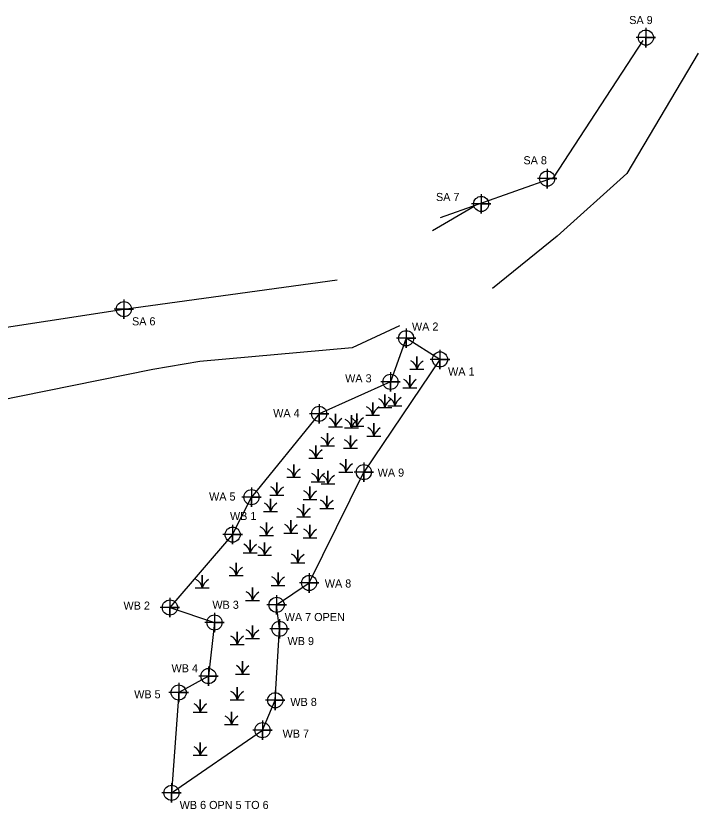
# Model space of a CAD drawing. Extents: x 2058476 to 2058911, y 688598 to 689103.
# Drawn here: x 2058700 to 2058910.8, y 688598.2 to 688843.3 of the extents above; entities that cross this region are included whole.
import ezdxf

# ---------------------------------------------------------------- set-up
doc = ezdxf.new("R2010")
doc.units = 0
for name, color, linetype in [('Exist Environmental Wetland Boundary', 7, 'Continuous'), ('Exist Environmental Wetland Boundary Cogo Comment', 7, 'Continuous'), ('Exist Environmental Wetland Boundary Cogo Point CELL', 7, 'Continuous'), ('Exist Hydro Jurisdictional Stream or Body of Water NEU Mitigable', 7, 'Continuous'), ('Exist Hydro Jurisdictional Stream or Body of Water NEU Mitigable Cogo Comment', 7, 'Continuous'), ('Exist Hydro Jurisdictional Stream or Body of Water NEU Mitigable Cogo Point CELL', 7, 'Continuous'), ('Exist Hydro Swamp or Marsh', 7, 'Continuous')]:
    doc.layers.add(name, color=color, linetype=linetype)

msp = doc.modelspace()

# ---------------------------------------------------------------- linework, layer by layer
at = {"layer": 'Exist Environmental Wetland Boundary'}
for p, q in [((2058831.07, 688737.12), (2058807.52, 688702.3)), ((2058767, 688682.98), (2058772.83, 688694.56)), ((2058781.46, 688653.85), (2058780.59, 688661.27))]:
    msp.add_line(p, q, dxfattribs=at)
for points in [[(2058831.07, 688737.12), (2058820.62, 688743.65), (2058815.77, 688730.19), (2058793.71, 688720.32), (2058772.83, 688694.56)], [(2058780.59, 688661.27), (2058790.64, 688668.04), (2058807.52, 688702.3)], [(2058767, 688682.98), (2058747.61, 688660.45), (2058761.37, 688655.84), (2058759.51, 688639.28), (2058750.32, 688634.18), (2058748.12, 688603.2), (2058776.2, 688622.56), (2058780.17, 688631.79), (2058781.46, 688653.85)], [(2058767, 688682.98), (2058747.61, 688660.45), (2058761.37, 688655.84), (2058759.51, 688639.28), (2058750.32, 688634.18), (2058748.12, 688603.2), (2058776.2, 688622.56), (2058780.17, 688631.79), (2058781.46, 688653.85)]]:
    msp.add_lwpolyline(points, dxfattribs=at)
at = {"layer": 'Exist Environmental Wetland Boundary Cogo Point CELL'}
for points in [[(2058820.62, 688746.65), (2058820.62, 688740.65), (2058820.62, 688743.65), (2058823.62, 688743.65), (2058817.62, 688743.65)], [(2058831.07, 688740.12), (2058831.07, 688734.12), (2058831.07, 688737.12), (2058834.07, 688737.12), (2058828.07, 688737.12)], [(2058815.77, 688733.19), (2058815.77, 688727.19), (2058815.77, 688730.19), (2058818.77, 688730.19), (2058812.77, 688730.19)], [(2058793.71, 688723.32), (2058793.71, 688717.32), (2058793.71, 688720.32), (2058796.71, 688720.32), (2058790.71, 688720.32)], [(2058807.52, 688705.3), (2058807.52, 688699.3), (2058807.52, 688702.3), (2058810.52, 688702.3), (2058804.52, 688702.3)], [(2058772.83, 688697.56), (2058772.83, 688691.56), (2058772.83, 688694.56), (2058775.83, 688694.56), (2058769.83, 688694.56)], [(2058767, 688685.98), (2058767, 688679.98), (2058767, 688682.98), (2058770, 688682.98), (2058764, 688682.98)], [(2058767, 688685.98), (2058767, 688679.98), (2058767, 688682.98), (2058770, 688682.98), (2058764, 688682.98)], [(2058790.64, 688671.04), (2058790.64, 688665.04), (2058790.64, 688668.04), (2058793.64, 688668.04), (2058787.64, 688668.04)], [(2058780.59, 688664.27), (2058780.59, 688658.27), (2058780.59, 688661.27), (2058783.59, 688661.27), (2058777.59, 688661.27)], [(2058747.61, 688663.45), (2058747.61, 688657.45), (2058747.61, 688660.45), (2058750.61, 688660.45), (2058744.61, 688660.45)], [(2058747.61, 688663.45), (2058747.61, 688657.45), (2058747.61, 688660.45), (2058750.61, 688660.45), (2058744.61, 688660.45)], [(2058761.37, 688658.84), (2058761.37, 688652.84), (2058761.37, 688655.84), (2058764.37, 688655.84), (2058758.37, 688655.84)], [(2058761.37, 688658.84), (2058761.37, 688652.84), (2058761.37, 688655.84), (2058764.37, 688655.84), (2058758.37, 688655.84)], [(2058781.46, 688656.85), (2058781.46, 688650.85), (2058781.46, 688653.85), (2058784.46, 688653.85), (2058778.46, 688653.85)], [(2058781.46, 688656.85), (2058781.46, 688650.85), (2058781.46, 688653.85), (2058784.46, 688653.85), (2058778.46, 688653.85)], [(2058759.51, 688642.28), (2058759.51, 688636.28), (2058759.51, 688639.28), (2058762.51, 688639.28), (2058756.51, 688639.28)], [(2058759.51, 688642.28), (2058759.51, 688636.28), (2058759.51, 688639.28), (2058762.51, 688639.28), (2058756.51, 688639.28)], [(2058750.32, 688637.18), (2058750.32, 688631.18), (2058750.32, 688634.18), (2058753.32, 688634.18), (2058747.32, 688634.18)], [(2058750.32, 688637.18), (2058750.32, 688631.18), (2058750.32, 688634.18), (2058753.32, 688634.18), (2058747.32, 688634.18)], [(2058780.17, 688634.79), (2058780.17, 688628.79), (2058780.17, 688631.79), (2058783.17, 688631.79), (2058777.17, 688631.79)], [(2058780.17, 688634.79), (2058780.17, 688628.79), (2058780.17, 688631.79), (2058783.17, 688631.79), (2058777.17, 688631.79)], [(2058776.2, 688625.56), (2058776.2, 688619.56), (2058776.2, 688622.56), (2058779.2, 688622.56), (2058773.2, 688622.56)], [(2058776.2, 688625.56), (2058776.2, 688619.56), (2058776.2, 688622.56), (2058779.2, 688622.56), (2058773.2, 688622.56)], [(2058748.12, 688606.2), (2058748.12, 688600.2), (2058748.12, 688603.2), (2058751.12, 688603.2), (2058745.12, 688603.2)], [(2058748.12, 688606.2), (2058748.12, 688600.2), (2058748.12, 688603.2), (2058751.12, 688603.2), (2058745.12, 688603.2)]]:
    msp.add_lwpolyline(points, dxfattribs=at)
for centre in [(2058820.62, 688743.65), (2058831.07, 688737.12), (2058815.77, 688730.19), (2058793.71, 688720.32), (2058807.52, 688702.3), (2058772.83, 688694.56), (2058767, 688682.98), (2058767, 688682.98), (2058790.64, 688668.04), (2058747.61, 688660.45), (2058747.61, 688660.45), (2058780.59, 688661.27), (2058761.37, 688655.84), (2058761.37, 688655.84), (2058781.46, 688653.85), (2058781.46, 688653.85), (2058759.51, 688639.28), (2058759.51, 688639.28), (2058750.32, 688634.18), (2058750.32, 688634.18), (2058780.17, 688631.79), (2058780.17, 688631.79), (2058776.2, 688622.56), (2058776.2, 688622.56), (2058748.12, 688603.2), (2058748.12, 688603.2)]:
    msp.add_circle(centre, 2.34, dxfattribs=at)
at = {"layer": 'Exist Hydro Jurisdictional Stream or Body of Water NEU Mitigable'}
msp.add_line((2058841.67, 688784.35), (2058828.75, 688776.81), dxfattribs=at)
for points in [[(2058893.77, 688835.68), (2058866.04, 688793.18), (2058831.1, 688780.86)], [(2058910.85, 688831.72), (2058888.78, 688794.57), (2058867.24, 688775.19), (2058847.32, 688759.04)], [(2058546.88, 688798.43), (2058567.07, 688780.26), (2058597.17, 688776.35), (2058637.95, 688744.91), (2058686.27, 688745.42), (2058733.39, 688752.64), (2058799.32, 688761.71)], [(2058818.52, 688747.47), (2058803.98, 688740.74), (2058756.88, 688736.43), (2058742.34, 688734.01), (2058709.24, 688727.28), (2058672.09, 688719.74), (2058647.32, 688720.28), (2058620.41, 688732.93), (2058577.76, 688738.46), (2058551.38, 688751.92), (2058524.85, 688774.39)]]:
    msp.add_lwpolyline(points, dxfattribs=at)
at = {"layer": 'Exist Hydro Jurisdictional Stream or Body of Water NEU Mitigable Cogo Point CELL'}
for points in [[(2058894.71, 688839.54), (2058894.71, 688833.54), (2058894.71, 688836.54), (2058897.71, 688836.54), (2058891.71, 688836.54)], [(2058864.21, 688795.97), (2058864.21, 688789.97), (2058864.21, 688792.97), (2058867.21, 688792.97), (2058861.21, 688792.97)], [(2058843.82, 688788.15), (2058843.82, 688782.15), (2058843.82, 688785.15), (2058846.82, 688785.15), (2058840.82, 688785.15)], [(2058733.39, 688755.64), (2058733.39, 688749.64), (2058733.39, 688752.64), (2058736.39, 688752.64), (2058730.39, 688752.64)]]:
    msp.add_lwpolyline(points, dxfattribs=at)
for centre in [(2058894.71, 688836.54), (2058864.21, 688792.97), (2058843.82, 688785.15), (2058733.39, 688752.64)]:
    msp.add_circle(centre, 2.34, dxfattribs=at)
at = {"layer": 'Exist Hydro Swamp or Marsh'}
for points in [[(2058821.75, 688734.07), (2058823.9, 688734.07), (2058823.9, 688738.01), (2058823.9, 688734.07), (2058826.05, 688734.07)], [(2058819.6, 688728.32), (2058821.75, 688728.32), (2058821.75, 688732.27), (2058821.75, 688728.32), (2058823.9, 688728.32)], [(2058811.87, 688722.29), (2058814.02, 688722.29), (2058814.02, 688726.23), (2058814.02, 688722.29), (2058816.17, 688722.29)], [(2058814.93, 688722.76), (2058817.09, 688722.76), (2058817.09, 688726.71), (2058817.09, 688722.76), (2058819.24, 688722.76)], [(2058808.12, 688719.89), (2058810.27, 688719.89), (2058810.27, 688723.83), (2058810.27, 688719.89), (2058812.42, 688719.89)], [(2058803.27, 688716.48), (2058805.42, 688716.48), (2058805.42, 688720.43), (2058805.42, 688716.48), (2058807.57, 688716.48)], [(2058796.63, 688716.3), (2058798.78, 688716.3), (2058798.78, 688720.25), (2058798.78, 688716.3), (2058800.93, 688716.3)], [(2058801.55, 688715.95), (2058803.7, 688715.95), (2058803.7, 688719.89), (2058803.7, 688715.95), (2058805.85, 688715.95)], [(2058808.47, 688713.43), (2058810.63, 688713.43), (2058810.63, 688717.37), (2058810.63, 688713.43), (2058812.78, 688713.43)], [(2058794.12, 688710.38), (2058796.27, 688710.38), (2058796.27, 688714.32), (2058796.27, 688710.38), (2058798.42, 688710.38)], [(2058801.3, 688709.66), (2058803.45, 688709.66), (2058803.45, 688713.61), (2058803.45, 688709.66), (2058805.6, 688709.66)], [(2058790.53, 688706.61), (2058792.68, 688706.61), (2058792.68, 688710.56), (2058792.68, 688706.61), (2058794.83, 688706.61)], [(2058799.86, 688702.3), (2058802.01, 688702.3), (2058802.01, 688706.25), (2058802.01, 688702.3), (2058804.16, 688702.3)], [(2058783.71, 688700.69), (2058785.86, 688700.69), (2058785.86, 688704.63), (2058785.86, 688700.69), (2058788.01, 688700.69)], [(2058791.23, 688699.29), (2058793.38, 688699.29), (2058793.38, 688703.23), (2058793.38, 688699.29), (2058795.53, 688699.29)], [(2058794.3, 688698.71), (2058796.45, 688698.71), (2058796.45, 688702.66), (2058796.45, 688698.71), (2058798.6, 688698.71)], [(2058778.51, 688695.13), (2058780.66, 688695.13), (2058780.66, 688699.07), (2058780.66, 688695.13), (2058782.81, 688695.13)], [(2058788.74, 688693.87), (2058790.89, 688693.87), (2058790.89, 688697.81), (2058790.89, 688693.87), (2058793.04, 688693.87)], [(2058776.53, 688690.1), (2058778.68, 688690.1), (2058778.68, 688694.05), (2058778.68, 688690.1), (2058780.83, 688690.1)], [(2058793.94, 688691), (2058796.09, 688691), (2058796.09, 688694.94), (2058796.09, 688691), (2058798.24, 688691)], [(2058786.76, 688688.49), (2058788.91, 688688.49), (2058788.91, 688692.43), (2058788.91, 688688.49), (2058791.06, 688688.49)], [(2058775.28, 688682.74), (2058777.43, 688682.74), (2058777.43, 688686.69), (2058777.43, 688682.74), (2058779.58, 688682.74)], [(2058782.81, 688683.46), (2058784.96, 688683.46), (2058784.96, 688687.41), (2058784.96, 688683.46), (2058787.11, 688683.46)], [(2058788.74, 688682.03), (2058790.89, 688682.03), (2058790.89, 688685.97), (2058790.89, 688682.03), (2058793.04, 688682.03)], [(2058770.24, 688677.37), (2058772.39, 688677.37), (2058772.39, 688681.32), (2058772.39, 688677.37), (2058774.54, 688677.37)], [(2058774.74, 688676.64), (2058776.89, 688676.64), (2058776.89, 688680.59), (2058776.89, 688676.64), (2058779.04, 688676.64)], [(2058784.97, 688674.31), (2058787.12, 688674.31), (2058787.12, 688678.25), (2058787.12, 688674.31), (2058789.27, 688674.31)], [(2058765.89, 688670.31), (2058768.05, 688670.31), (2058768.05, 688674.25), (2058768.05, 688670.31), (2058770.2, 688670.31)], [(2058755.4, 688666.51), (2058757.55, 688666.51), (2058757.55, 688670.45), (2058757.55, 688666.51), (2058759.7, 688666.51)], [(2058778.87, 688667.31), (2058781.02, 688667.31), (2058781.02, 688671.26), (2058781.02, 688667.31), (2058783.17, 688667.31)], [(2058770.96, 688662.66), (2058773.11, 688662.66), (2058773.11, 688666.6), (2058773.11, 688662.66), (2058775.26, 688662.66)], [(2058770.96, 688650.93), (2058773.11, 688650.93), (2058773.11, 688654.88), (2058773.11, 688650.93), (2058775.26, 688650.93)], [(2058766.21, 688649.03), (2058768.36, 688649.03), (2058768.36, 688652.97), (2058768.36, 688649.03), (2058770.51, 688649.03)], [(2058767.89, 688639.88), (2058770.04, 688639.88), (2058770.04, 688643.83), (2058770.04, 688639.88), (2058772.19, 688639.88)], [(2058766.21, 688631.91), (2058768.36, 688631.91), (2058768.36, 688635.86), (2058768.36, 688631.91), (2058770.51, 688631.91)], [(2058754.81, 688628.11), (2058756.96, 688628.11), (2058756.96, 688632.06), (2058756.96, 688628.11), (2058759.11, 688628.11)], [(2058764.45, 688624.31), (2058766.6, 688624.31), (2058766.6, 688628.25), (2058766.6, 688624.31), (2058768.75, 688624.31)], [(2058754.81, 688614.8), (2058756.96, 688614.8), (2058756.96, 688618.75), (2058756.96, 688614.8), (2058759.11, 688614.8)]]:
    msp.add_lwpolyline(points, dxfattribs=at)
for centre, radius, start, end in [((2058820.84, 688733.84), 3.07, 4.1403, 67.535), ((2058828.46, 688732.55), 4.81, 122.1274, 161.6222), ((2058818.68, 688728.1), 3.07, 4.1403, 67.535), ((2058826.31, 688726.81), 4.81, 122.1274, 161.6222), ((2058814.02, 688722.54), 3.07, 4.1403, 67.535), ((2058821.65, 688721.25), 4.81, 122.1274, 161.6222), ((2058810.95, 688722.07), 3.07, 4.1403, 67.535), ((2058818.58, 688720.77), 4.81, 122.1274, 161.6222), ((2058807.2, 688719.67), 3.07, 4.1403, 67.535), ((2058814.83, 688718.37), 4.81, 122.1274, 161.6222), ((2058795.71, 688716.08), 3.07, 4.1403, 67.535), ((2058803.34, 688714.79), 4.81, 122.1274, 161.6222), ((2058800.63, 688715.73), 3.07, 4.1403, 67.535), ((2058802.35, 688716.26), 3.07, 4.1403, 67.535), ((2058808.26, 688714.43), 4.81, 122.1274, 161.6222), ((2058809.98, 688714.97), 4.81, 122.1274, 161.6222), ((2058807.56, 688713.21), 3.07, 4.1403, 67.535), ((2058815.19, 688711.91), 4.81, 122.1274, 161.6222), ((2058793.2, 688710.16), 3.07, 4.1403, 67.535), ((2058800.83, 688708.86), 4.81, 122.1274, 161.6222), ((2058800.38, 688709.44), 3.07, 4.1403, 67.535), ((2058808.01, 688708.15), 4.81, 122.1274, 161.6222), ((2058789.61, 688706.39), 3.07, 4.1403, 67.535), ((2058797.24, 688705.1), 4.81, 122.1274, 161.6222), ((2058782.79, 688700.47), 3.07, 4.1403, 67.535), ((2058790.42, 688699.17), 4.81, 122.1274, 161.6222), ((2058798.94, 688702.08), 3.07, 4.1403, 67.535), ((2058806.57, 688700.79), 4.81, 122.1274, 161.6222), ((2058790.32, 688699.07), 3.07, 4.1403, 67.535), ((2058797.94, 688697.77), 4.81, 122.1274, 161.6222), ((2058793.38, 688698.49), 3.07, 4.1403, 67.535), ((2058801.01, 688697.2), 4.81, 122.1274, 161.6222), ((2058777.59, 688694.9), 3.07, 4.1403, 67.535), ((2058785.22, 688693.61), 4.81, 122.1274, 161.6222), ((2058787.82, 688693.65), 3.07, 4.1403, 67.535), ((2058795.45, 688692.35), 4.81, 122.1274, 161.6222), ((2058793.02, 688690.78), 3.07, 4.1403, 67.535), ((2058800.65, 688689.48), 4.81, 122.1274, 161.6222), ((2058775.62, 688689.88), 3.07, 4.1403, 67.535), ((2058783.24, 688688.59), 4.81, 122.1274, 161.6222), ((2058785.84, 688688.26), 3.07, 4.1403, 67.535), ((2058793.47, 688686.97), 4.81, 122.1274, 161.6222), ((2058781.9, 688683.24), 3.07, 4.1403, 67.535), ((2058774.36, 688682.52), 3.07, 4.1403, 67.535), ((2058781.99, 688681.23), 4.81, 122.1274, 161.6222), ((2058789.52, 688681.95), 4.81, 122.1274, 161.6222), ((2058787.82, 688681.8), 3.07, 4.1403, 67.535), ((2058795.45, 688680.51), 4.81, 122.1274, 161.6222), ((2058769.32, 688677.15), 3.07, 4.1403, 67.535), ((2058776.95, 688675.86), 4.81, 122.1274, 161.6222), ((2058773.82, 688676.42), 3.07, 4.1403, 67.535), ((2058781.45, 688675.13), 4.81, 122.1274, 161.6222), ((2058784.05, 688674.09), 3.07, 4.1403, 67.535), ((2058791.68, 688672.79), 4.81, 122.1274, 161.6222), ((2058764.98, 688670.09), 3.07, 4.1403, 67.535), ((2058772.61, 688668.79), 4.81, 122.1274, 161.6222), ((2058754.48, 688666.28), 3.07, 4.1403, 67.535), ((2058762.11, 688664.99), 4.81, 122.1274, 161.6222), ((2058777.95, 688667.09), 3.07, 4.1403, 67.535), ((2058785.58, 688665.8), 4.81, 122.1274, 161.6222), ((2058770.05, 688662.44), 3.07, 4.1403, 67.535), ((2058777.67, 688661.14), 4.81, 122.1274, 161.6222), ((2058770.05, 688650.71), 3.07, 4.1403, 67.535), ((2058777.67, 688649.42), 4.81, 122.1274, 161.6222), ((2058765.3, 688648.81), 3.07, 4.1403, 67.535), ((2058772.92, 688647.51), 4.81, 122.1274, 161.6222), ((2058766.97, 688639.66), 3.07, 4.1403, 67.535), ((2058774.6, 688638.37), 4.81, 122.1274, 161.6222), ((2058765.3, 688631.69), 3.07, 4.1403, 67.535), ((2058772.92, 688630.4), 4.81, 122.1274, 161.6222), ((2058753.89, 688627.89), 3.07, 4.1403, 67.535), ((2058761.52, 688626.6), 4.81, 122.1274, 161.6222), ((2058763.53, 688624.09), 3.07, 4.1403, 67.535), ((2058771.16, 688622.79), 4.81, 122.1274, 161.6222), ((2058753.89, 688614.58), 3.07, 4.1403, 67.535), ((2058761.52, 688613.28), 4.81, 122.1274, 161.6222)]:
    msp.add_arc(centre, radius, start, end, dxfattribs=at)

# ---------------------------------------------------------------- texts
at = {"layer": 'Exist Environmental Wetland Boundary Cogo Comment'}
for s, p in [('WA 2', (2058822.4, 688746.01)), ('WA 1', (2058833.57, 688732.12)), ('WA 3', (2058801.76, 688730.03)), ('WA 4', (2058779.52, 688719.26)), ('WA 9', (2058811.81, 688700.89)), ('WA 5', (2058759.71, 688693.5)), ('WB 1', (2058766.17, 688687.5)), ('WB 1', (2058766.17, 688687.5)), ('WA 8', (2058795.47, 688666.63)), ('WB 2', (2058733.26, 688659.8)), ('WB 2', (2058733.26, 688659.8)), ('WB 3', (2058760.73, 688660.05)), ('WB 3', (2058760.73, 688660.05)), ('WA 7 OPEN', (2058783.09, 688656.27)), ('WB 9', (2058783.96, 688648.85)), ('WB 9', (2058783.96, 688648.85)), ('WB 4', (2058748.1, 688640.44)), ('WB 4', (2058748.1, 688640.44)), ('WB 5', (2058736.56, 688632.4)), ('WB 5', (2058736.56, 688632.4)), ('WB 8', (2058784.83, 688630.04)), ('WB 8', (2058784.83, 688630.04)), ('WB 7', (2058782.43, 688620.24)), ('WB 7', (2058782.43, 688620.24)), ('WB 6 OPN 5 TO 6', (2058750.62, 688598.2)), ('WB 6 OPN 5 TO 6', (2058750.62, 688598.2))]:
    msp.add_text(s, height=2.5, dxfattribs=at).set_placement(p)
at = {"layer": 'Exist Hydro Jurisdictional Stream or Body of Water NEU Mitigable Cogo Comment'}
for s, p in [('SA 9', (2058889.55, 688840.73)), ('SA 8', (2058856.86, 688797.4)), ('SA 7', (2058829.83, 688786.06)), ('SA 6', (2058735.89, 688747.64))]:
    msp.add_text(s, height=2.5, dxfattribs=at).set_placement(p)

doc.saveas('drawing.dxf')
